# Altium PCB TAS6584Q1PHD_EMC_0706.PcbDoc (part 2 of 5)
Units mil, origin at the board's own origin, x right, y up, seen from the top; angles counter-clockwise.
Board outline 7086.61 x 5118.11 mil, 6 copper layers (Top Layer, GND02, SIG03, SIG04, GND05, Bottom Layer), stack 60.484 mil thick; 461 components, 247 nets, 1337 pads, 1658 vias.
Unrouted connection lines stored in the file: 67.
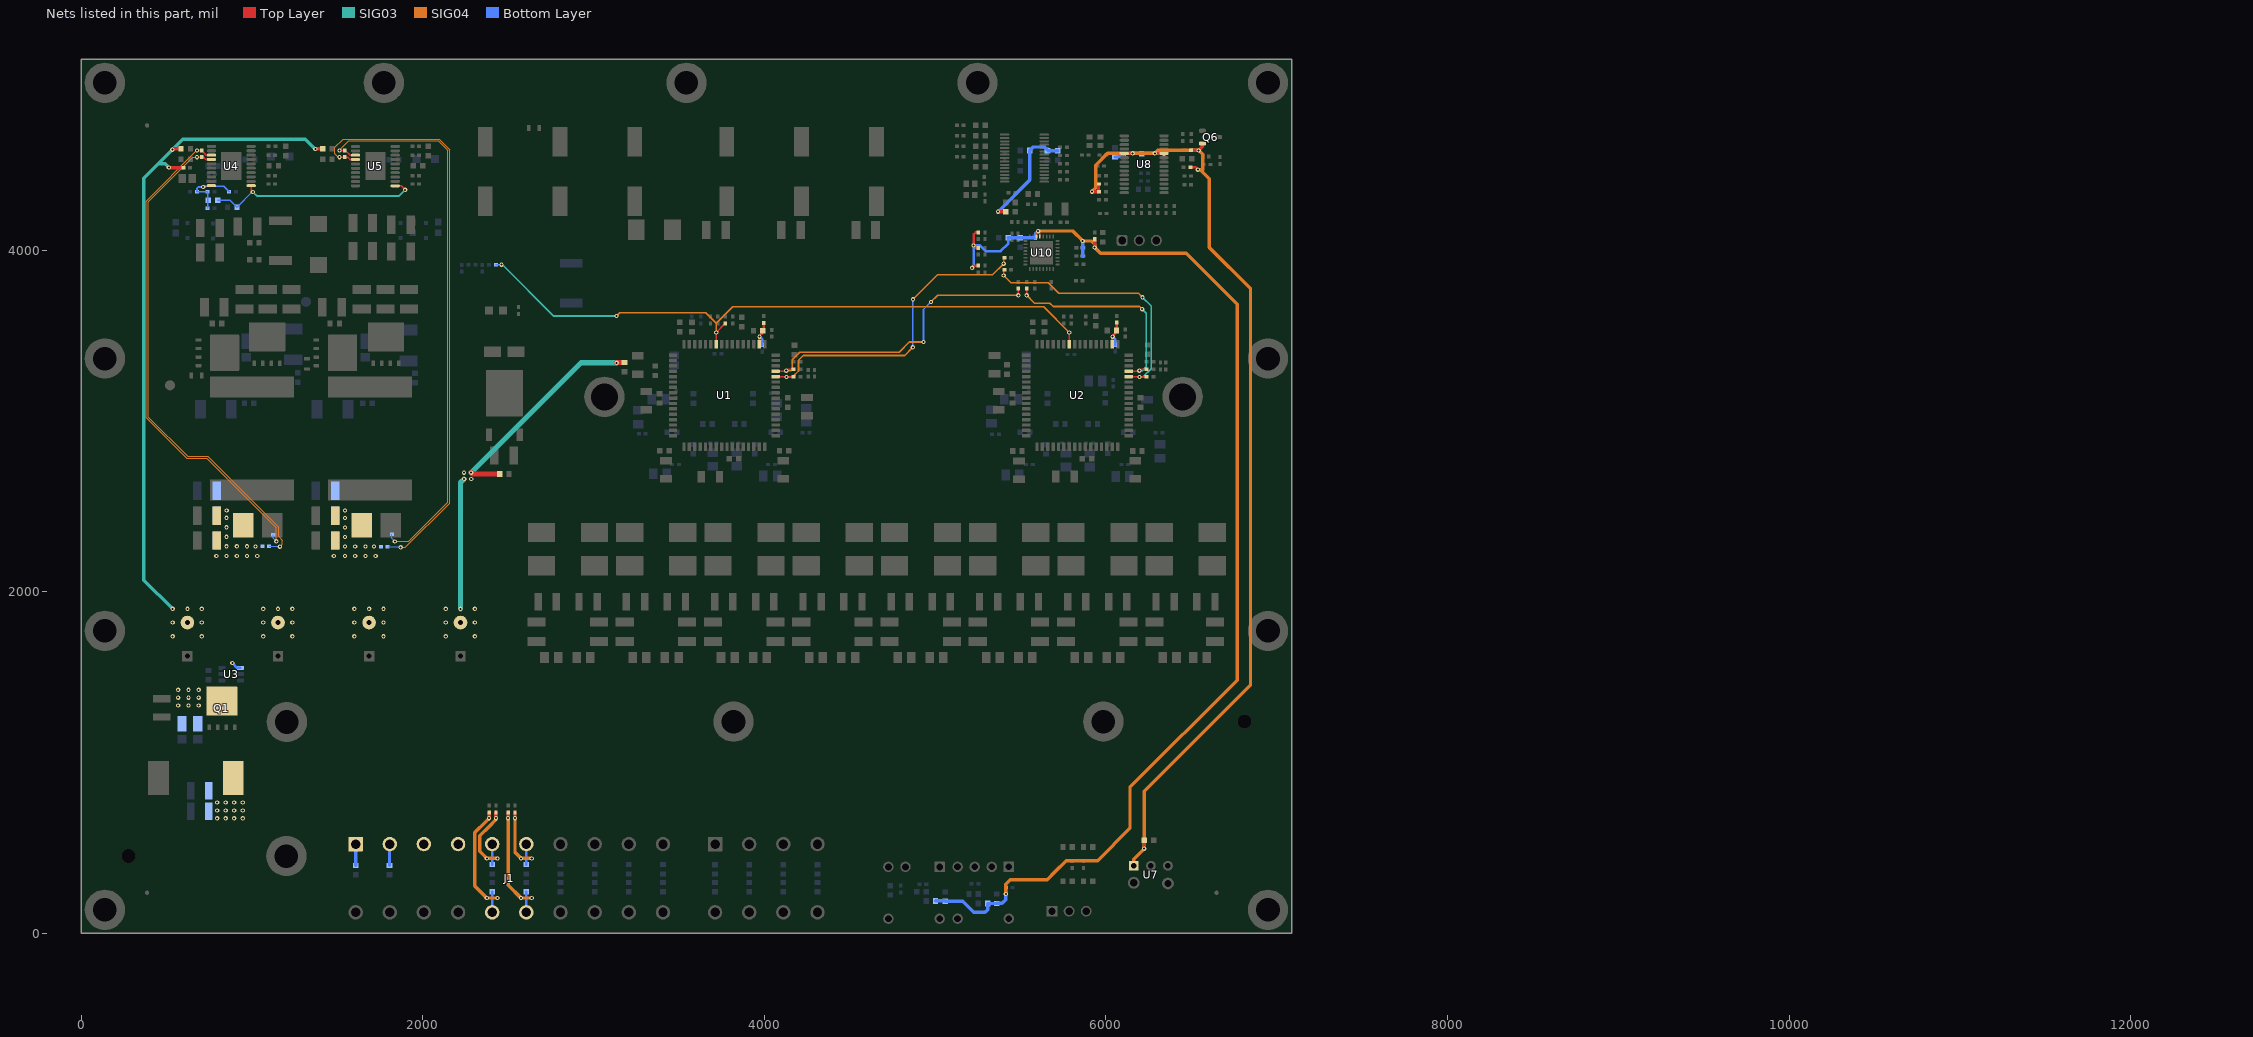
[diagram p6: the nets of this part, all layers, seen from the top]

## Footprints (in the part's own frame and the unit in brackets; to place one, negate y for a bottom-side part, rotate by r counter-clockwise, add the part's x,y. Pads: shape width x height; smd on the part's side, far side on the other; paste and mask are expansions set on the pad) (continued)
NDP0003B_N [mm] "D-PAK, 4-Leads, Body 6.1x6.6mm, Pitch 2.29mm, Lead Span 9.7mm, IPC Medium Density"
  rrect11% 1.9x0.95 smd: 1(-4.35,2.28) 3(-4.35,-2.28)
  rrect2% 6.9x5.5 smd: 4(1.85,0)
  silkscreen extent -4.47,-3.35 -2,3.43, body extent -2.5,-3.35 3.7,3.35, height 2.38
PA2512 [mm]
  rect 3.05x3.68 smd: 1(-2.16,0) 2(2.16,0)
  silkscreen extent -4,-2.2 4,2.2, body extent -3.3,-1.71 3.3,1.71, height 0.88
Panasonic_B [mm] "SMD, 2-Leads, Dia 4mm"
  rrect6% 2.5x1.6 smd: 1(-1.75,0) 2(1.75,0)
  silkscreen extent -2,-2.15 2.15,2.15, body extent -2.15,-2.15 2.15,2.15, height 6.1
PLR135_T10 [mm] "EVERLIGHT"
  rect 1.45x1.45 hole 0.813: 1(2.54,-4.67)
  round 1.45 hole 0.813: 2(0,-4.67) 3(-2.54,-4.67)
  round 1.75 hole 1.092: 4(2.54,-2.13) 5(-2.54,-2.04)
  silkscreen extent -5.05,-6.93 5.05,6.95, body extent -5,-6.9 5,6.9, height 10.3
PW0028A_N [mm] "TSOP, 28-Leads, Body 9.7x4.4mm, Pitch 0.65mm, IPC Medium Density"
  oval 1.4x0.45 smd: 1(-2.95,4.225) 2(-2.95,3.575) 3(-2.95,2.925) 4(-2.95,2.275) 5(-2.95,1.625) 6(-2.95,0.975) 7(-2.95,0.325) 8(-2.95,-0.325) 9(-2.95,-0.975) 10(-2.95,-1.625) 11(-2.95,-2.275) 12(-2.95,-2.925) 13(-2.95,-3.575) 14(-2.95,-4.225) 15(2.95,-4.225) 16(2.95,-3.575) 17(2.95,-2.925) 18(2.95,-2.275) 19(2.95,-1.625) 20(2.95,-0.975) 21(2.95,-0.325) 22(2.95,0.325) 23(2.95,0.975) 24(2.95,1.625) 25(2.95,2.275) 26(2.95,2.925) 27(2.95,3.575) 28(2.95,4.225)
  silkscreen extent -3.5,-4.9 1.5,4.9, body extent -3.21,-4.85 3.21,4.85, height 1
PWP0020A_N [mm] "TSOP, 20-Leads, Body 6.5x4.4mm, Pitch 0.65mm, Exposed Pad, IPC Medium Density"
  rrect100% 1.4x0.45 smd: 1(-2.95,2.925) 2(-2.95,2.275) 3(-2.95,1.625) 4(-2.95,0.975) 5(-2.95,0.325) 6(-2.95,-0.325) 7(-2.95,-0.975) 8(-2.95,-1.625) 9(-2.95,-2.275) 10(-2.95,-2.925) 11(2.95,-2.925) 12(2.95,-2.275) 13(2.95,-1.625) 14(2.95,-0.975) 15(2.95,-0.325) 16(2.95,0.325) 17(2.95,0.975) 18(2.95,1.625) 19(2.95,2.275) 20(2.95,2.925)
  rrect3% 3x4.2 smd: 21(0,0)
  silkscreen extent -3.55,-3.3 1.5,3.4, body extent -3.21,-3.25 3.21,3.25, height 1
QFP64-PHD [mm] "TQFP, 64-Leads, Body 14x14mm, Pitch 0.8mm, Thermal Pad 8x8mm, IPC High Density"
  rrect20% 1.25x0.5 smd: 1(-7.625,6) 2(-7.625,5.2) 3(-7.625,4.4) 4(-7.625,3.6) 5(-7.625,2.8) 6(-7.625,2) 7(-7.625,1.2) 8(-7.625,0.4) 9(-7.625,-0.4) 10(-7.625,-1.2) 11(-7.625,-2) 12(-7.625,-2.8) 13(-7.625,-3.6) 14(-7.625,-4.4) 15(-7.625,-5.2) 16(-7.625,-6) 33(7.625,-6) 34(7.625,-5.2) 35(7.625,-4.4) 36(7.625,-3.6) 37(7.625,-2.8) 38(7.625,-2) 39(7.625,-1.2) 40(7.625,-0.4) 41(7.625,0.4) 42(7.625,1.2) 43(7.625,2) 44(7.625,2.8) 45(7.625,3.6) 46(7.625,4.4) 47(7.625,5.2) 48(7.625,6)
  rrect20% 0.5x1.25 smd: 17(-6,-7.625) 18(-5.2,-7.625) 19(-4.4,-7.625) 20(-3.6,-7.625) 21(-2.8,-7.625) 22(-2,-7.625) 23(-1.2,-7.625) 24(-0.4,-7.625) 25(0.4,-7.625) 26(1.2,-7.625) 27(2,-7.625) 28(2.8,-7.625) 29(3.6,-7.625) 30(4.4,-7.625) 31(5.2,-7.625) 32(6,-7.625) 49(6,7.625) 50(5.2,7.625) 51(4.4,7.625) 52(3.6,7.625) 53(2.8,7.625) 54(2,7.625) 55(1.2,7.625) 56(0.4,7.625) 57(-0.4,7.625) 58(-1.2,7.625) 59(-2,7.625) 60(-2.8,7.625) 61(-3.6,7.625) 62(-4.4,7.625) 63(-5.2,7.625) 64(-6,7.625)
  silkscreen extent -8.13,-7.12 7.12,7.12, body extent -7.02,-7.02 7.02,7.02, height 1.21
RHB0032E [mm] "QFN, 32-Leads, Body 5x5mm, Pitch 0.5mm, Thermal Pad 3.45x3.45mm, TI Recommended"
  oval 0.6x0.24 smd: 1(-2.4,1.75) 2(-2.4,1.25) 3(-2.4,0.75) 4(-2.4,0.25) 5(-2.4,-0.25) 6(-2.4,-0.75) 7(-2.4,-1.25) 8(-2.4,-1.75) 17(2.4,-1.75) 18(2.4,-1.25) 19(2.4,-0.75) 20(2.4,-0.25) 21(2.4,0.25) 22(2.4,0.75) 23(2.4,1.25) 24(2.4,1.75)
  oval 0.24x0.6 smd: 9(-1.75,-2.4) 10(-1.25,-2.4) 11(-0.75,-2.4) 12(-0.25,-2.4) 13(0.25,-2.4) 14(0.75,-2.4) 15(1.25,-2.4) 16(1.75,-2.4) 25(1.75,2.4) 26(1.25,2.4) 27(0.75,2.4) 28(0.25,2.4) 29(-0.25,2.4) 30(-0.75,2.4) 31(-1.25,2.4) 32(-1.75,2.4)
  rect 3.45x3.45 smd paste-1.725: 33(0,0)
  silkscreen extent -2.72,-2.73 2.72,2.73, body extent -2.57,-2.57 2.58,2.58, height 1.01
SOD-123F [mm] "NXP recommended land pattern"
  rect 1.2x1.2 smd paste-0.05: 1(-1.4,0) 2(1.4,0)
  silkscreen extent -2.64,-1.12 2.01,1.12, body extent -1.8,-0.85 1.8,0.85, height 1.2
SOD-123HE [mm] "SMD, 2-Leads, Body 2.8x1.8mm"
  rect 2.3x1.4 smd: 1(-0.9,0)
  rect 1.25x1.4 smd: 2(1.425,0)
  silkscreen extent -2.7,-1.1 2,1.1, body extent -1.5,-0.98 1.5,0.98, height 1
SOD-323 [mm] "NXP recommended land pattern"
  rect 0.6x0.6 smd paste-0.05: 1(-1.1,0) 2(1.1,0)
  silkscreen extent -2.06,-0.86 1.53,0.86, body extent -1.3,-0.67 1.3,0.68, height 1.1
SOT-23 [mm] "SOT23, 3-Leads, Body 2.9x1.3mm, Pitch 0.95mm, Lead Span 2.5mm, IPC Medium Density"
  rrect50% 1x0.6 smd: 1(-1.2,0.95) 2(-1.2,-0.95) 3(1.2,0)
  silkscreen extent -1.63,-1.5 0.7,1.5, body extent -1.16,-1.45 1.21,1.45, height 1
SRP1265a [mm] "BOURNS"
  rect 3.1x5 smd: 1(-5.55,0) 2(5.55,0)
  silkscreen extent -7,-6.5 7,6.5, body extent -6.95,-6.4 6.95,6.4, height 6.4
SRP1770TA [mm] "SMD, 2-Leads, Body 16.9x16.9mm"
  rect 3.15x12.5 smd: 1(-7.675,0) 2(7.675,0)
  silkscreen extent -8.45,-8.45 8.45,8.45, body extent -8.65,-8.45 8.65,8.45, height 6.7
SRP7030F_3 [mm] "BOURNS"
  rect 2.4x2.5 smd: 1(-3.1,0) 2(3,0)
  silkscreen extent -3.4,-3.4 3.4,3.4, body extent -3.35,-3.35 3.35,3.35, height 3
TI_Stacked_Overlay_Small [mil]
  silkscreen extent -418,-98 418,98
WEEE_Minimum [mil] "WEEElie bin"
  silkscreen extent -95,-172 99,104
Wurth_61300311021 [mm] "Header, 2.54 mm, 3x1, R/A, TH"
  rect 1.6x1.6 hole 1.1: 1(-2.54,0)
  round 1.6 hole 1.1: 2(0,0) 3(2.54,0)
  silkscreen extent -4.25,-4.04 3.81,-1.5, body extent -3.81,-10.04 3.81,0.32, height 2.55
WURTH_61300311121 [mm] "Header, 2.54mm, 3x1, TH"
  rrect50% 1.65x1.65 hole 1.15: 1(-2.54,0)
  round 1.65 hole 1.15: 2(0,0) 3(2.54,0)
  body extent -3.81,-1.27 3.81,1.27, height 8.54
XTAL_ABM10 [mm] "ABRACON"
  rect 0.8x0.9 smd: 1(-0.625,0.825) 2(-0.625,-0.825) 3(0.625,-0.825) 4(0.625,0.825)
  silkscreen extent -1.28,-0.13 1.05,1.52, body extent -1.05,-1.3 1.05,1.3, height 0.7

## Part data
C1 C10 C11 C13 C14 C59 C68 C69 C71 C72 C124 C127 C137 C141 C181 C203 C219: library part CMP-0007139-1, "CAP, CERM, 1 uF, 25 V, +/- 10%, X7R, AEC-Q200 Grade 1, 0603", Cap_Case=0603, Manufacturer=MuRata, Supplier Part Number 1=490-10673-1-ND, TempCo=X7R, Tolerance_%=10%, Value1=Unknown, Value2=25V, ValueDisplayed=1uF
C2 C3 C4 C5 C17 C18 C60 C61 C62 C63 C75 C76: library part CMP-0750040-1, "CAP, CERM, 1 µF, 100 V,+/- 10%, X7R, AEC-Q200 Grade 1, 1206", Cap_Case=1206, Manufacturer=MuRata, TempCo=X7R, Tolerance_%=10%, Value2=100V, ValueDisplayed=1µF
C6 C7 C8 C9 C15 C16 C64 C65 C66 C67 C73 C74: library part CMP-0064935-4, "CAP, CERM, 0.1 uF, 100 V,+/- 10%, X7R, AEC-Q200 Grade 1, 0603", Cap_Case=0603, Manufacturer=MuRata, Supplier Part Number 1=490-13420-1-ND, TempCo=X7R, Tolerance_%=10%, Value1=Unknown, Value2=100V, ValueDisplayed=0.1uF
C12 C70 C128: library part CMP-0083622-1, "CAP, CERM, 2.2 µF, 25 V,+/- 10%, X7R, AEC-Q200 Grade 1, 0805", Cap_Case=0805, Manufacturer=MuRata, Supplier Part Number 1=490-4787-1-ND, TempCo=X7R, Tolerance_%=10%, Value2=25V, ValueDisplayed=2.2µF
C19 C20 C21 C22 C23 C24 C25 C26 C77 C78 C79 C80 C81 C82 C83 C84 C132 C144: library part CMP-0007145-1, "CAP, CERM, 0.22 uF, 50 V, +/- 10%, X7R, AEC-Q200 Grade 1, 0603", Cap_Case=0603, Manufacturer=MuRata, Supplier Part Number 1=490-5402-1-ND, TempCo=X7R, Tolerance_%=10%, Value1=Unknown, Value2=50V, ValueDisplayed=0.22uF
C27 C28 C29 C30 C31 C32 C33 C34 C85 C86 C87 C88 C89 C90 C91 C92: library part CMP-0006707-2, "CAP, CERM, 330 pF, 100 V, +/- 10%, X7R, 0402", Cap_Case=0402, Manufacturer=MuRata, Supplier Part Number 1=GRM155R72A331KA01D-ND, TempCo=X7R, Tolerance_%=10%, Value1=Unknown, Value2=100V, ValueDisplayed=330pF
C35 C36 C37 C38 C39 C40 C41 C42 C93 C94 C95 C96 C97 C98 C99 C100: library part CMP-0009232-1, "CAP, CERM, 2.2 uF, 100 V, +/- 10%, X7R, 1210", Cap_Case=1210, Manufacturer=MuRata, Supplier Part Number 1=490-3385-1-ND, TempCo=X7R, Tolerance_%=10%, Value1="0.007 ohm", Value2=100V, ValueDisplayed=2.2uF
C43 C44 C45 C46 C47 C48 C49 C50 C101 C102 C103 C104 C105 C106 C107 C108: library part CMP-0008022-1, "CAP, CERM, 0.47 uF, 50 V, +/- 10%, X7R, AEC-Q200 Grade 1, 0805", Cap_Case=0805, Manufacturer=MuRata, PartNumber=GCM21BR71H474KA55L, Supplier Part Number 1=490-4788-1-ND, TempCo=X7R, Tolerance_%=10%, Value1=Unknown, Value2=50V, ValueDisplayed=0.47uF
C51 C52 C53 C54 C55 C56 C57 C58 C109 C110 C111 C112 C113 C114 C115 C116 C122 C190 C191 C192 C193: library part CMP-0007174-3, "CAP, CERM, 0.01 uF, 50 V, +/- 5%, C0G/NP0, 0603", Cap_Case=0603, Manufacturer=MuRata, Supplier Part Number 1=490-9666-1-ND, TempCo=C0G/NP0, Tolerance_%=5%, Value1=Unknown, Value2=50V, ValueDisplayed=0.01uF
C117 C119 C126: library part CMP-0009228-2, "CAP, CERM, 4.7 uF, 50 V, +/- 10%, X7R, 1210", Cap_Case=1210, Manufacturer=MuRata, Supplier Part Number 1=490-1864-1-ND, TempCo=X7R, Tolerance_%=10%, Value1="0.002 ohm", Value2=50V, ValueDisplayed=4.7uF
C118 C184: library part CMP-0007463-1, "CAP, CERM, 0.068 uF, 50 V, +/- 10%, X7R, 0603", Cap_Case=0603, Manufacturer=MuRata, Supplier Part Number 1=490-3288-1-ND, TempCo=X7R, Tolerance_%=10%, Value1=Unknown, Value2=50V, ValueDisplayed=0.068uF
C120 C123 C187 C189: library part CMP-0007203-1, "CAP, CERM, 270 pF, 50 V, +/- 5%, C0G/NP0, 0603", Cap_Case=0603, Manufacturer=MuRata, Supplier Part Number 1=490-1437-1-ND, TempCo=C0G/NP0, Tolerance_%=5%, Value1=Unknown, Value2=50V, ValueDisplayed=270pF
C121 C158 C159 C166 C167: library part CMP-0007470-1, "CAP, CERM, 0.1 uF, 100 V, +/- 10%, X7R, 0603", Cap_Case=0603, Manufacturer=MuRata, Supplier Part Number 1=490-6439-1-ND, TempCo=X7R, Tolerance_%=10%, Value1=Unknown, Value2=100V, ValueDisplayed=0.1uF
C125 C129 C179 C182 C201 C205 C207 C209 C212 C213 C228 C229 C230: "CAP, CERM, 0.1 uF, 16 V, +/- 10%, X7R, 0402", Cap_Case=0402, Manufacturer=MuRata, PartNumber=GRM155R71C104KA88D, Supplier Part Number 1=490-3261-1-ND, TempCo=X7R, Tolerance_%=10%, Value1=Unknown, Value2=16V, ValueDisplayed=0.1uF
C130 C142: library part CMP-0006682-1, "CAP, CERM, 220 pF, 50 V, +/- 10%, X7R, 0402", Cap_Case=0402, Manufacturer=MuRata, Supplier Part Number 1=490-1298-1-ND, TempCo=X7R, Tolerance_%=10%, Value1=Unknown, Value2=50V, ValueDisplayed=220pF
C131 C133 C135 C136: library part CMP-0093073-1, "2200 µF 25 V Aluminum Electrolytic Capacitors Radial, Can - 10000 Hrs @ 105°C", Digikey Part Number=493-6873-ND, Leakage Current=550uA, Manufacturer=Nichicon, Mouser Part Number=647-UHW1E222MHD, Operating Temperature Range="-40°C to +105°C", Tolerance_%=20%, ValueDisplayed=2200uF
C134 C145: library part CMP-0007498-1, "CAP, CERM, 4.7 uF, 10 V, +/- 20%, X7R, 0603", Cap_Case=0603, Manufacturer=MuRata, TempCo=X7R, Tolerance_%=20%, Value1=Unknown, Value2=10V, ValueDisplayed=4.7uF
C138 C139 C140 C146 C147 C148 C149 C150 C151 C152 C153 C160 C161 C162 C163 C164 C165 C168 C220 C221 C222 C223 C224 C225 C226 C227: library part CMP-0009226-3, "CAP, CERM, 10 uF, 50 V, +/- 10%, X7R, 1210", Cap_Case=1210, Manufacturer=MuRata, Supplier Part Number 1=490-6544-1-ND, TempCo=X7R, Tolerance_%=10%, Value1=Unknown, Value2=50V, ValueDisplayed=10uF
C143: library part CMP-0860542-1, "CAP, AL, 47 µF, 16 V, +/- 20%, 0.85 ohm, AEC-Q200 Grade 2, SMD", Cap_Case=B, Manufacturer=Panasonic, Tolerance_%=20%, Value1="0.85 ohm", Value2=16V, ValueDisplayed=47µF
C154 C155 C156 C157 C218: library part CMP-0007131-1, "CAP, CERM, 1000 pF, 100 V, +/- 5%, C0G/NP0, AEC-Q200 Grade 1, 0603", Cap_Case=0603, Manufacturer=MuRata, Supplier Part Number 1=490-4772-1-ND, TempCo=C0G/NP0, Tolerance_%=5%, Value1=Unknown, Value2=100V, ValueDisplayed=1000pF
C169 C170 C171 C172 C173 C174: library part CMP-0093066-1, "330 µF 50 V Aluminum Electrolytic Capacitors Radial, Can - SMD 120mOhm @ 100kHz 2000 Hrs @ 105°C", Digikey Part Number=565-5155-1-ND, Leakage Current=165uA, Manufacturer="United Chemi-Con", Mouser Part Number=661-EMZR500ARA331MJA, Operating Temperature Range="-55°C to +105°C", Tolerance_%=20%, ValueDisplayed=330uF
C175 C176 C194 C195 C196 C197 C198 C202 C204 C206 C208 C210 C211 C214 C215: library part CMP-0007497-1, "CAP, CERM, 10 uF, 10 V, +/- 20%, X7R, 0603", Cap_Case=0603, Manufacturer=MuRata, Supplier Part Number 1=81-GRM188Z71A106MA3D, TempCo=X7R, Tolerance_%=20%, Value1=Unknown, Value2=10V, ValueDisplayed=10uF
C177 C180 C199 C200: library part CMP-0006436-1, "CAP, CERM, 20 pF, 50 V, +/- 5%, C0G/NP0, 0402", Cap_Case=0402, Manufacturer=MuRata, Supplier Part Number 1=81-GRM1555C1H200JA1D, TempCo=C0G/NP0, Tolerance_%=5%, Value1=Unknown, Value2=50V, ValueDisplayed=20pF
C178 C185 C186 C188: "CAP, CERM, 10 pF, 50 V, +/- 5%, C0G/NP0, 0402", Cap_Case=0402, Manufacturer=MuRata, PartNumber=GRM1555C1H100JA01D, Supplier Part Number 1=81-GRM1555C1H100JA1D, TempCo=C0G/NP0, Tolerance_%=5%, Value1=Unknown, Value2=50V, ValueDisplayed=10pF
C183: "CAP, CERM, 4700 pF, 25 V, +/- 10%, X7R, 0402", Cap_Case=0402, Manufacturer=MuRata, PartNumber=GRM155R71E472KA01D, Supplier Part Number 1=490-1309-1-ND, TempCo=X7R, Tolerance_%=10%, Value1=Unknown, Value2=25V, ValueDisplayed=4700pF
C216 C217: library part CMP-0006375-1, "CAP, CERM, 12 pF, 25 V, +/- 5%, C0G/NP0, 0402", Cap_Case=0402, Manufacturer=MuRata, Supplier Part Number 1=81-GRM1555C1E120JA1D, TempCo=C0G/NP0, Tolerance_%=5%, Value1=Unknown, Value2=25V, ValueDisplayed=12pF
D1 D2 D10 D11: library part CMP-0028825-2, "Diode, Schottky, 60 V, 3 A, AEC-Q101, SOD-123HE", Manufacturer="Fairchild Semiconductor", Value1=3A, Value2=0.65V
D3 D4: library part CMP-0028377-1, "Diode, Schottky, 60 V, 1 A, SOD-123F", Manufacturer=Nexperia, Supplier Part Number 1=568-4104-1-ND, Value1=1A, Value2=0.57V
D5: "LED, Green, SMD", Color=Green, Manufacturer=Lite-On, PartNumber=LTST-C170KGKT, Supplier Part Number 1=160-1414-1-ND, Value1=W, Value2=2V
D6 D7 D8 D9: library part CMP-0028455-1, "Diode, Schottky, 30 V, 0.2 A, SOD-323", Manufacturer="ON Semiconductor", Supplier Part Number 1=BAT54HT1OSCT-ND, Value1=0.2A, Value2=0.35V
D12 D13: "LED, Blue, SMD", Color=blue, Manufacturer=Rohm, PartNumber=SMLP12BC7TT86, Supplier Part Number 1=511-1615-1-ND, Value1=W, Value2=2.9V
FID1 FID2 FID3 FID4 FID5 FID6: library part CMP-0077181-1, "Fiducial mark.  There is nothing to buy or mount.", Manufacturer=N/A
H1: library part Heatsink, "TAS6584 EMI board heatsink", Alternate Manufacturer=-
J1: library part CMP-0087217-1, "TERM BLOCK HDR 20POS 5.08MM", Current_A=10A, Manufacturer="Phoenix Contact", Voltage_V=320V
J2: library part CMP-0093062-1, Current_A=10A, Digikey Part Number=277-1401-ND, Manufacturer="Phoenix Contact", Mouser Part Number=651-1736713, Operating Temperature Range="-40°C to +100°C", Voltage_V=320V
J3: library part CMP-0054795-1, "Header, 2.54 mm, 3x1, Gold, R/A, TH", Color=Black, Manufacturer="Wurth Elektronik", Supplier Part Number 1=732-5336-ND
J4: library part CMP-0054796-2, "Header, 2.54 mm, 3x1, Gold, TH", Color=Black, Manufacturer="Wurth Elektronik", Supplier Part Number 1=732-5316-ND
J5: library part CMP-0075020-1, "JUMPER TIN SMD", Manufacturer=Harwin, PartNumber=S1911-46R, Supplier Part Number 1=952-1740-1-ND
L1 L11 L15 L16 L17 L18 L19: library part CMP-0003347-2, "Ferrite Bead, 600 ohm @ 100 MHz, 0.5 A, 0603", Manufacturer=MuRata, Supplier Part Number 1=490-11031-1-ND, Value1="0.35 ohm", Value2=0.5A, ValueDisplayed="600 ohm"
L2 L3 L4 L5 L6 L7 L8 L9: library part CMP-0093075-1, "Power Choke Coil, 10uH 20% 100kHz, 22mΩ DCR max, Idc 5.8A, Isat 10A", Manufacturer=Cyntec, Operating Temperature Range="-55°C to +125°C", Test Frequency=100kHz, Tolerance_%=20%
L10: library part CMP-0056908-1, "Inductor, Shielded, 1 uH, 30 A, 0.0017 ohm, AEC-Q200 Grade 0, SMD", Manufacturer=Bourns, Supplier Part Number 1=SRP1265A-1R0MCT-ND, Value1="0.0017 ohm", Value2=30A, ValueDisplayed=1uH
L12 L13: library part CMP-0081211-1, "Inductor, Shielded, Powdered Iron, 4.7 µH, 25 A, 0.0055 ohm, AEC-Q200 Grade 0, SMD", Manufacturer=Bourns, Supplier Part Number 1=SRP1770TA-4R7MCT-ND, Value1="0.0055 ohm", Value2=25A, ValueDisplayed=4.7µH
L14: library part CMP-0056994-1, "Inductor, Flat Wire, Powdered Iron, 200 nH, 23 A, 0.0024 ohm, SMD", Manufacturer=Bourns, Supplier Part Number 1=652-SRP7030-R20FM, Value1="0.0024 ohm", Value2=23A, ValueDisplayed=200nH
Logo1: library part CMP-0074838-1, "Texas Instrument Corporate Signature"
Logo2: library part CMP-0074847-1, "FCC_disclaimer"
Logo3: library part CMP-0074769-1
Logo4: library part CMP-0074844-1
MP1: library part CMP-0093198-1, Digikey Part Number=732-3670378-ND, Manufacturer="Wurth Electronics", Mouser Part Number=710-3670378, Operating Temperature Range="-40°C to +125°C"
MP2: library part CMP-0093199-1, Digikey Part Number=732-3670548-ND, Manufacturer="Wurth Electronics", Mouser Part Number=710-3670548, Operating Temperature Range="-40°C to +125°C"
Q1: library part CMP-0000274-1, "MOSFET, N-CH, 25 V, 100 A, DNK0008A (VSON-CLIP-8)", Alternate Manufacturer=None, Manufacturer="Texas Instruments", Supplier Part Number 1=CSD16570Q5B-ND, Value1=0, Value2="192 nC"
Q2 Q3 Q4 Q5: library part CMP-0000823-2, "MOSFET, N-CH, 60 V, 100 A, DNK0008A (VSON-CLIP-8)", Alternate Manufacturer=None, Manufacturer="Texas Instruments", Supplier Part Number 1=296-41076-1-ND, Value1=0.003, Value2="41 nC"
Q6: library part CMP-0000325-2, "Transistor, PNP, 40 V, 0.2 A, SOT-23", Manufacturer="Fairchild Semiconductor", Supplier Part Number 1=MMBT3906FSCT-ND, Value1="0.2 A", Value2=300
R1 R3 R5: library part CMP-0026231-2, "RES, 2.20 k, 1%, 0.063 W, AEC-Q200 Grade 0, 0402", Manufacturer=Vishay-Dale, Power_W=63mW, Supplier Part Number 1=541-2.20KLCT-ND, TempCo="100 ppm/C", Tolerance_%=1%, Value2=0.063W, Value_Code=2k20, ValueDisplayed=2.20k
R2 R4 R6 R7 R10 R11 R32 R33 R35 R36 R39 R40 R52 R65 R66 R75 R127 R128 R129 R130 R131 R132 R133 R134 R135 R155 R157 R160: "RES, 10.0 k, 1%, 0.063 W, AEC-Q200 Grade 0, 0402", Manufacturer=Vishay-Dale, PartNumber=CRCW040210K0FKED, Power_W=63mW, Supplier Part Number 1=541-10.0KLCT-ND, TempCo="100 ppm/C", Tolerance_%=1%, Value2=0.063W, Value_Code=10k0, ValueDisplayed=10.0k
R8 R38 R67: library part CMP-0026822-3, "RES, 0, 5%, 0.063 W, AEC-Q200 Grade 0, 0402", Manufacturer=Vishay-Dale, PartNumber=CRCW04020000Z0ED, Power_W=63mW, Supplier Part Number 1=541-0.0JCT-ND, TempCo="200 ppm/C", Tolerance_%=5%, Value2=0.063W, Value_Code=0000, ValueDisplayed=0
R9 R12 R14 R15 R37 R41 R43 R44 R76 R77 R83 R84 R125 R126 R144 R145 R146 R147 R149 R151 R152 R153 R154 R158 R159: library part CMP-0026822-3, "RES, 0, 5%, 0.063 W, AEC-Q200 Grade 0, 0402", Manufacturer=Vishay-Dale, Power_W=63mW, Supplier Part Number 1=541-0.0JCT-ND, TempCo="200 ppm/C", Tolerance_%=5%, Value2=0.063W, Value_Code=0000, ValueDisplayed=0
R13 R42: library part CMP-0025958-3, "RES, 10.0 k, 1%, 0.063 W, AEC-Q200 Grade 0, 0402", Manufacturer=Vishay-Dale, PartNumber=CRCW040210K0FKED, Power_W=63mW, Supplier Part Number 1=541-10.0KLCT-ND, TempCo="100 ppm/C", Tolerance_%=1%, Value2=0.063W, Value_Code=10k0, ValueDisplayed=10.0k
R16 R17 R18 R19 R20 R21 R22 R23 R34 R45 R46 R47 R48 R49 R50 R51: library part CMP-0020448-3, "RES, 10, 5%, 0.125 W, AEC-Q200 Grade 0, 0805", Manufacturer=Vishay-Dale, Power_W=125mW, Supplier Part Number 1=541-10ACT-ND, TempCo="200 ppm/C", Tolerance_%=5%, Value2=0.125W, Value_Code=10R0, ValueDisplayed=10
R24 R25 R26 R27 R28 R29 R30 R31 R53 R54 R55 R56 R57 R58 R59 R60 R103 R104 R105: library part CMP-0015361-2, "RES, 0, 5%, 0.25 W, 1210", Manufacturer=Rohm, Power_W=250mW, Supplier Part Number 1=RHM0.0BECT-ND, TempCo="20 ppm/C", Tolerance_%=5%, Value2=0.25W, Value_Code=0000, ValueDisplayed=0
R61: library part CMP-0025950-1, "RES, 100 k, 1%, 0.063 W, 0402", Manufacturer=Vishay-Dale, Power_W=63mW, Supplier Part Number 1=541-100KLCT-ND, TempCo="100 ppm/C", Tolerance_%=1%, Value2=0.063W, Value_Code=100k
R62: library part CMP-0026506-1, "RES, 68.1 k, 1%, 0.063 W, 0402", Manufacturer=Vishay-Dale, Power_W=63mW, Supplier Part Number 1=541-68.1KLCT-ND, TempCo="100 ppm/C", Tolerance_%=1%, Value2=0.063W, Value_Code=68k1, ValueDisplayed=68.1k
R63: library part CMP-0026336-2, "RES, 3.57 k, 1%, 0.063 W, AEC-Q200 Grade 0, 0402", Manufacturer=Vishay-Dale, Power_W=63mW, Supplier Part Number 1=541-3.57KLCT-ND, TempCo="100 ppm/C", Tolerance_%=1%, Value2=0.063W, Value_Code=3k57, ValueDisplayed=3.57k
R64 R72: library part CMP-0026542-2, "RES, 750, 1%, 0.063 W, AEC-Q200 Grade 0, 0402", Manufacturer=Vishay-Dale, Power_W=63mW, Supplier Part Number 1=541-750LCT-ND, TempCo="100 ppm/C", Tolerance_%=1%, Value2=0.063W, Value_Code=750R, ValueDisplayed=750
R69: library part CMP-0026284-2, "RES, 30.1 k, 1%, 0.063 W, AEC-Q200 Grade 0, 0402", Manufacturer=Vishay-Dale, Power_W=63mW, Supplier Part Number 1=541-30.1KLCT-ND, TempCo="100 ppm/C", Tolerance_%=1%, Value2=0.063W, Value_Code=30k1, ValueDisplayed=30.1k
R70: library part CMP-0026556-2, "RES, 7.68 k, 1%, 0.063 W, AEC-Q200 Grade 0, 0402", Manufacturer=Vishay-Dale, Power_W=63mW, Supplier Part Number 1=541-7.68KLCT-ND, TempCo="100 ppm/C", Tolerance_%=1%, Value2=0.063W, Value_Code=7k68, ValueDisplayed=7.68k
R71 R81 R138 R142: library part CMP-0025805-4, "RES, 3.3, 5%, 0.1 W, AEC-Q200 Grade 0, 0603", Manufacturer=Vishay-Dale, Power_W=100mW, Supplier Part Number 1=541-3.3GCT-ND, TempCo="200 ppm/C", Tolerance_%=5%, Value2=0.1W, Value_Code=3R30, ValueDisplayed=3.3
R73 R74 R82: library part CMP-0026162-2, "RES, 20.0 k, 1%, 0.063 W, AEC-Q200 Grade 0, 0402", Manufacturer=Vishay-Dale, Power_W=63mW, Supplier Part Number 1=541-20.0KLCT-ND, TempCo="100 ppm/C", Tolerance_%=1%, Value2=0.063W, Value_Code=20k0, ValueDisplayed=20.0k
R80 R139 R140 R141 R148 R150: library part CMP-0026822-3, "RES, 0, 5%, 0.063 W, AEC-Q200 Grade 0, 0402", Manufacturer=Vishay-Dale, PartNumber=CRCW04020000Z0ED, Power_W=63mW, Supplier Part Number 1=541-0.0JCT-ND, TempCo="200 ppm/C", Tolerance_%=5%, Value2=0.063W, Value_Code=0000
R86 R124 R136 R137 R143: library part CMP-0026852-3, "RES, 1.0 k, 5%, 0.063 W, AEC-Q200 Grade 0, 0402", Manufacturer=Vishay-Dale, Power_W=63mW, Supplier Part Number 1=541-1.0KJCT-ND, TempCo="200 ppm/C", Tolerance_%=5%, Value2=0.063W, Value_Code=1k00, ValueDisplayed=1.0k
R87 R88 R91 R92: library part CMP-0026852-1, "RES, 1.0 k, 5%, 0.063 W, 0402", Manufacturer=Vishay-Dale, Power_W=63mW, Supplier Part Number 1=541-1.0KJCT-ND, TempCo="200 ppm/C", Tolerance_%=5%, Value2=0.063W, Value_Code=1k00, ValueDisplayed=1.0k
R89 R90: library part CMP-0015833-2, "RES, 0.003, 1%, 1 W, AEC-Q200 Grade 0, 2512", Manufacturer="Yageo America", Power_W=1W, Supplier Part Number 1=YAG2138CT-ND, TempCo="100 ppm/C", Tolerance_%=1%, Value_Code=3L000, ValueDisplayed=0.003
R93 R94 R99 R100: library part CMP-0016186-1, "RES, 8.2, 5%, 0.75 W, AEC-Q200 Grade 0, 2010", Manufacturer=Vishay-Dale, Power_W=750mW, Supplier Part Number 1=541-8.2WCT-ND, TempCo="200 ppm/C", Tolerance_%=5%, Value2=0.75W, Value_Code=8R20, ValueDisplayed=8.2
R95 R96 R97 R98: library part CMP-0025776-4, "RES, 2.0, 5%, 0.1 W, AEC-Q200 Grade 0, 0603", Manufacturer=Vishay-Dale, Power_W=100mW, Supplier Part Number 1=541-2.0GCT-ND, TempCo="200 ppm/C", Tolerance_%=5%, Value2=0.1W, Value_Code=2R00, ValueDisplayed=2.0
R101: library part CMP-0016021-1, "RES, 0.68, 5%, 1 W, 2512", Manufacturer=Panasonic, Power_W=1W, Supplier Part Number 1=PT.68UCT-ND, TempCo="200 ppm/C", Tolerance_%=5%, Value_Code=R680, ValueDisplayed=0.68
R102: library part CMP-0015431-1, "RES, 10.0 k, 1%, 1 W, AEC-Q200 Grade 0, 2512", Manufacturer=Vishay-Dale, Power_W=1W, Supplier Part Number 1=541-10.0KAFCT-ND, TempCo="100 ppm/C", Tolerance_%=1%, Value_Code=10k0, ValueDisplayed=10.0k
R106 R114 R115 R116 R117 R122 R123: "RES, 49.9, 1%, 0.063 W, AEC-Q200 Grade 0, 0402", Manufacturer=Vishay-Dale, PartNumber=CRCW040249R9FKED, Power_W=63mW, Supplier Part Number 1=541-49.9LCT-ND, TempCo="100 ppm/C", Tolerance_%=1%, Value2=0.063W, Value_Code=49R9, ValueDisplayed=49.9
R107: "RES, 100 k, 1%, 0.063 W, AEC-Q200 Grade 0, 0402", Manufacturer=Vishay-Dale, PartNumber=CRCW0402100KFKED, Power_W=63mW, Supplier Part Number 1=541-100KLCT-ND, TempCo="100 ppm/C", Tolerance_%=1%, Value2=0.063W, Value_Code=100k
R108 R113: library part CMP-0026414-2, "RES, 4.99 k, 1%, 0.063 W, AEC-Q200 Grade 0, 0402", Manufacturer=Vishay-Dale, PartNumber=CRCW04024K99FKED, Power_W=63mW, Supplier Part Number 1=541-4.99KLCT-ND, TempCo="100 ppm/C", Tolerance_%=1%, Value2=0.063W, Value_Code=4k99, ValueDisplayed=4.99k
R109 R111 R112 R119: "RES, 4.99 k, 1%, 0.063 W, AEC-Q200 Grade 0, 0402", Manufacturer=Vishay-Dale, PartNumber=CRCW04024K99FKED, Power_W=63mW, Supplier Part Number 1=541-4.99KLCT-ND, TempCo="100 ppm/C", Tolerance_%=1%, Value2=0.063W, Value_Code=4k99, ValueDisplayed=4.99k
R110: library part CMP-0026934-3, "RES, 470, 5%, 0.063 W, AEC-Q200 Grade 0, 0402", Manufacturer=Vishay-Dale, Power_W=63mW, Supplier Part Number 1=541-470JCT-ND, TempCo="200 ppm/C", Tolerance_%=5%, Value2=0.063W, Value_Code=470R, ValueDisplayed=470
R118: "RES, 681, 1%, 0.063 W, AEC-Q200 Grade 0, 0402", Manufacturer=Vishay-Dale, PartNumber=CRCW0402681RFKED, Power_W=63mW, Supplier Part Number 1=541-681LCT-ND, TempCo="100 ppm/C", Tolerance_%=1%, Value2=0.063W, Value_Code=681R, ValueDisplayed=681
R120 R121 R156: library part CMP-0025817-1, "RES, 4.7 k, 5%, 0.1 W, 0603", Manufacturer=Vishay-Dale, Power_W=100mW, Supplier Part Number 1=541-4.7KGCT-ND, TempCo="200 ppm/C", Tolerance_%=5%, Value2=0.1W, Value_Code=4k70, ValueDisplayed=4.7k
R161: library part CMP-0026935-3, "RES, 47 k, 5%, 0.063 W, AEC-Q200 Grade 0, 0402", Manufacturer=Vishay-Dale, Power_W=63mW, Supplier Part Number 1=541-47KJCT-ND, TempCo="200 ppm/C", Tolerance_%=5%, Value2=0.063W, Value_Code=47k0, ValueDisplayed=47k
RT1 RT2 RT3: library part CMP-0054545-2, "Thermistor NTC, 10.0k ohm, 0.5%, 0603", Manufacturer=MuRata, Power_W=100mW, Tolerance_%=0.5%
U1 U2: "20W Inductor-Less, Digital Input, Stereo, Closed-Loop Class-D Audio Amplifier with Enhanced Processing and and DirectPath HP Driver (DCP0038)", Alternate Manufacturer="Texas Instruments"
U3: library part CMP-0079180-1, "Low Iq Always ON Smart Diode Controller, DBV0006A (SOT-23-6)", Alternate Manufacturer="Texas Instruments", Alternate PartNumber=LM74700QDBVRQ1
U4 U5: library part CMP-0066110-1, "3-65V Wide Vin, Current Mode Synchronous Boost Controller with Multiphase Capability, PWP0020A (TSSOP-20)", Alternate Manufacturer="Texas Instruments", Alternate PartNumber=LM5122MHE/NOPB
U6: library part CMP-0070332-1, "800mA Low-Dropout Linear Regulator, 3-pin TO-252, Pb-Free", Manufacturer="Texas Instruments", PackageTopMarking=NSUZXYTT*LM1117*IDT-3.3, PowerWise=N
U7: "Photolink- Fiber Optic Receiver, TH", Manufacturer=Everlight, PartNumber=PLR135/T10, Supplier Part Number 1=1080-1433-ND
U8: library part CMP-0028713-1, "Automotive Catalog 96-kHz 24-Bit Digital Audio Interface Receiver, 50 ps Jitter, 3.3V, -40 to 85 degC, 28-Pin TSSOP (PW), Green (RoHS & no Sb/Br)", Manufacturer="Texas Instruments", PartNumber=DIR9001IPWQ1, Supply Voltage(s)(V)=3.3
U9: library part CMP-0065622-1, "110 dB 2ch S/W Controlled Audio ADC With Universal Front End, DBT0030A (TSSOP-30)", Alternate Manufacturer="Texas Instruments"
U10: library part CMP-0039653-1, "16 MHz Mixed Signal Microcontroller with 16 KB Flash, 512 B SRAM and 24 GPIOs, -40 to 85 degC, 32-pin QFN (RHB), Green (RoHS & no Sb/Br)", Frequency(MHz)=16, Manufacturer="Texas Instruments", Temp Sensor=Yes
U11: library part CMP-0093065-1, "RCVR OPT DC-50MBD 1MM POF", Digikey Part Number=516-2643-ND, Manufacturer=Broadcom, Max Supply Voltage=5.25V, Min Supply Voltage=3.135V, Mouser Part Number=630-AFBR-2624Z, Operating Temperature Range="-40°C to +85°C"
U12: library part CMP-0093064-1, "Fiber Optic Transmitter with Driver 650nm 50MBd 3.135V ~ 3.465V, 4.75V ~ 5.25V 21 mA", Digikey Part Number=516-2642-ND, Manufacturer=Broadcom, Max Supply Voltage=5.25V, Min Supply Voltage=3.135V, Mouser Part Number=630-AFBR-1624Z, Operating Temperature Range="-40°C to +85°C"
Y1 Y2: library part CMP-0004590-1, "Crystal, 24.576 MHz, 10pF, SMD", Frequency Stability=+/-20ppm, Frequency_Fixed=24.576MHz, Manufacturer="Abracon Corporation", Supplier Part Number 1=535-9094-1-ND
Y3: library part CMP-0078856-1, "Crystal, 32.768 KHz, 20 ppm, SMD", Frequency Tolerance="20 ppm", Frequency_Fixed=32.768kHz, Manufacturer="ECS Inc.", Supplier Part Number 1=XC1617CT-ND

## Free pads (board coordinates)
  round 236.22 / inner round 157.48 / far side round 236.22 hole 137.8: 2(3818.9,1240) 3(137.8,137.8) 3(137.8,3366.14) 3(137.8,4980.31) 3(137.8,1771.65) 3(1200.79,452.76) 3(1203.18,1237.77) 3(1771.65,4980.31) 3(3543.31,4980.31) 3(5248.03,4980.31) 3(5984.25,1240.16) 3(6948.82,137.8) 3(6948.82,3366.14) 3(6948.82,4980.31) 3(6948.82,1770.97)
  round 82.68 hole 82.68 unplated: 5(275.59,452.76) 5(6811.02,1240.16)
  rect 60x60 hole 30: 6(620.79,1623.36) 6(1151.41,1623.36) 6(1685.2,1623.36) 6(2220.3,1623.36)
  round 80 hole 30: 6(620.79,1820.22) 6(1151.41,1820.22) 6(1685.2,1820.22) 6(2220.3,1820.22)

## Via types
v1: diameter 25, hole 12, Top Layer to Bottom Layer, 1387 vias
v2: diameter 25, hole 12, Top Layer to Bottom Layer, tented both sides, 242 vias
v3: diameter 19.68, hole 7.87, Top Layer to Bottom Layer, 29 vias

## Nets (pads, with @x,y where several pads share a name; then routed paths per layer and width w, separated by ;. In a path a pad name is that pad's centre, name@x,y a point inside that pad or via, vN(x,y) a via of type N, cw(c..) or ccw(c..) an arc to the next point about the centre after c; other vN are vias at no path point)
3.3V-ADC: C194.1 L16.1 R138.2 R142.2 | length 661.3
  Top Layer w20: v1(5368.38,4226.25) R138.2@5413.77,4226.25
  Bottom Layer w20: v1(5368.38,4226.25) 5553.7,4411.57 R142.2@5553.7,4584.29 5574.41,4605 5638.57,4605 5660.77,4582.8 C194.1@5717,4582.8
3.3V-MCU: C208.1 C209.2 C214.1 C215.1 L17.1 L18.1 L19.1 R52.2 R65.2 R66.2 R155.2 R157.2 R160.2 R161.2 U10.29 U10.30 | length 7140.9
  Top Layer w10: U10.30@5593.18,4080.24 5593.18,4102.18 v1(5603,4112) 5612.87,4102.13 U10.29@5612.87,4080.24
  Top Layer w15: v1(5216.55,3896.98) 5230.26,3910.68 R66.2@5252.91,3910.68 ; R65.2@5252.91,4014.39 5237.88,4014.39 v1(5224.86,4027.41) 5224.86,4091.18 5239.11,4105.43 R52.2@5252.91,4105.43
  Top Layer w20: v1(5933.66,4016.33) R161.2@5933.66,4056.76
  SIG04 w20: v1@5413.89,230.67 5413.89,288.27 5440.58,314.96 5655.96,314.96 5700.19,359.19 5767.41,426.41 5952.41,426.41 6140.53,614.53 6140.53,855.47 6768,1482.93 6768,3684.8 6470.8,3982 5967.98,3982 v1(5933.66,4016.33) 5933.66,4034.35 5913.36,4054.64 v1(5863.73,4054.64) 5805.53,4112.84 5603.84,4112.84 v1(5603,4112)
  Bottom Layer w15: v1@5218.6,3902.09 5224.86,3908.36 v1(5224.86,4027.41) 5225.87,4028.42 5261.74,4028.42 5295.59,3994.56 5382.83,3994.56 5428.3,4040.03 L17.1@5428.3,4072.95
  Bottom Layer w20: L19.1@5001.76,190 5056.65,190 C215.1@5059.2,187.44 5161.01,187.44 5225.45,123 5291.57,123 5307.85,139.28 L18.1@5307.85,175 5360.23,175 C214.1@5360.46,175.24 5391.37,175.24 5413.57,197.44 v1(5413.57,230.35) 5413.89,230.67 R155.2@5413.89,268.53 ; L17.1@5428.3,4072.95 C208.1@5497.8,4072.95 C209.2@5587.13,4072.95 5587.13,4096.13 v1(5603,4112) ; R157.2@5863.73,3966.33 v1(5863.73,4054.64)
3.3V-SPDIF: C175.2 C176.1 C179.2 C182.2 L15.1 Q6.2 R107.2 R111.2 R112.1 R113.1 U7.1 U8.5 U8.24 | length 6098.2
  Top Layer w16: U8.5@6107.72,4567.56 v1(6156.44,4567.56) ; v1(6285.94,4567.56) U8.24@6340,4567.56 ; R107.2@6502.24,4486.81 6523.11,4486.81 v1(6538,4471.92)
  Top Layer w20: v1(5918,4343) 5956.38,4343 R112.1@5956.38,4388.19 ; v1(6223.9,496.1) C175.2@6223.9,545 ; R111.2@6502.24,4585 v1(6543,4585) 6565,4607 Q6.2@6565,4625.2
  SIG04 w20: v1(5918,4343) 5940,4365 5940,4498.65 6008.91,4567.56 v1(6156.44,4567.56) v1(6285.94,4567.56) 6303.38,4585 v1(6543,4585) 6566.61,4561.39 6566.61,4471.92 v1(6538,4471.92) ; U7.1@6162.9,395.86 6162.9,435.1 v1(6223.9,496.1) 6223.9,832.9 6846.61,1455.61 6846.61,3775.72 6606,4016.33 6606,4418.79 6552.88,4471.92
  Bottom Layer w16: C182.2@6107.72,4567.56 v1(6156.44,4567.56) ; v1(6285.94,4567.56) C179.2@6340,4567.56
  Bottom Layer w20: L15.1@6053.36,4546.06 6069.4,4546.06 6086.96,4563.62 C182.2@6107.72,4563.62 ; v1(6156.44,4567.56) 6208.62,4567.56 6210,4568.94 6211.38,4567.56 v1(6285.94,4567.56)
14_4V: C131.2 C133.2 C135.2 C136.2 C138.1 C139.1 C146.1 C147.1 C148.1 C149.1 C150.1 C151.1 C152.1 C153.1 D1.1 D2.1 L1.2 L11.1 pad.6@620.79,1820.22 pad.6@1151.41,1820.22 pad.6@1685.2,1820.22 pad.6@2220.3,1820.22 Q1.5 Q1.6 Q1.7 Q1.8 Q1.9@823.3,1359.96 R69.2 R71.2 R81.2 R87.1 R88.1 R89.1 R90.1 U3.4 | length 6135
  Top Layer w20: v1@509,4485.24 510.24,4484 R69.2@597.85,4484 ; v1(532.52,4589.33) 537.63,4594.44 R71.2@583.79,4594.44 ; v1(1370.03,4592.78) 1371.69,4594.44 R81.2@1412.84,4594.44
  Top Layer w30: v1(2282.8,2698.05) 2290.34,2690.51 L11.1@2449.33,2690.51 ; v1(3134.69,3341.14) 3136.64,3343.09 L1.2@3180.41,3343.09
  SIG03 w20: v1(511.95,4484.91) 490.79,4506.07 449.26,4506.07 ; v1(534.42,1900.5) 366,2068.92 366,4422.81 449.26,4506.07 ; v1(1370.03,4592.78) 1311.64,4651.17 594.36,4651.17 v1(532.52,4589.33) 449.26,4506.07
  SIG03 w30: v1(2220.69,1900.5) 2220.69,2640.03 v1(2241.63,2660.98) ; v1(2282.8,2698.05) 2925.89,3341.14 v1(3134.69,3341.14)
  Bottom Layer w15: v1(884.1,1582.6) 911.48,1555.21 U3.4@931.57,1555.21
  other v1: 566.85,1333.87 626.85,1333.87 686.85,1333.87 566.85,1380 626.85,1380 686.85,1380 566.85,1426.13 626.85,1426.13 686.85,1426.13 534.42,1739.64 704.9,1739.64 1065.03,1739.64 1235.51,1739.64 1598.82,1739.64 1769.3,1739.64 2133.92,1739.64 2304.4,1739.64 534.42,1820.22 704.9,1820.22 1065.03,1820.22 1235.51,1820.22 1598.82,1820.22 1769.3,1820.22 2133.92,1820.22 2304.4,1820.22 621.18,1900.5 704.9,1900.5 1065.03,1900.5 1151.8,1900.5 1235.51,1900.5 1598.82,1900.5 1685.58,1900.5 1769.3,1900.5 2133.92,1900.5 2304.4,1900.5 1478.61,2209.67 1543.92,2209.67 1603.76,2209.67 1663.59,2209.67 1723.43,2209.67 790.18,2210.44 850.49,2210.44 910.33,2210.44 970.16,2210.44 1030,2210.44 1020.11,2265.67 1543.92,2265.47 1603.76,2265.47 1663.59,2265.47 1713.43,2265.47 850.49,2266.24 910.33,2266.24 970.16,2266.24 850.49,2322.03 1543.92,2321.26 1543.92,2377.05 850.49,2377.83 1543.92,2432.85 850.49,2433.62 851.19,2476.16 1543.92,2476.16 2283.28,2660.98 2241.39,2697.81
\FAULT1: R6.1 R158.1 U1.61 | length 1831.5
  Top Layer w10: U1.61@4065.2,3291.73 4124.3,3291.73 v1(4127.82,3295.26) 4135.65,3303.09 R6.1@4171.31,3303.09 ; v1(5487,3736.46) R158.1@5487,3771.38
  SIG04 w10: v1(4127.82,3295.26) 4155.36,3295.26 4163.2,3303.09 4163.2,3358.95 4206.85,3402.6 4788.91,3402.6 4849.88,3463.57 v1(4931.25,3463.57) ; v1(4975,3697) 5014.46,3736.46 v1(5487,3736.46)
  Bottom Layer w10: v1(4931.25,3463.57) 4931.25,3653.25 v1(4975,3697)
\FAULT2: R35.1 R159.1 U2.61 | length 1253.8
  Top Layer w10: v1(5535.38,3736.46) R159.1@5535.38,3771.38 ; U2.61@6132.55,3291.73 6191.65,3291.73 v1(6195.18,3295.26) 6203.01,3303.09 R35.1@6238.67,3303.09
  SIG04 w10: v1(5535.38,3736.46) 5581.35,3690.5 5671.12,3690.5 5690.62,3671 6196.04,3671 v1(6212.04,3655)
  SIG03 w10: v1(6195.18,3295.26) 6213.2,3295.26 6236.63,3318.68 6236.63,3630.41 v1(6212.04,3655)
\STBY1: R4.1 R147.2 U1.60 | length 1889.8
  Top Layer w10: U1.60@4065.2,3260.24 4127.25,3260.24 v1(4128.92,3258.57) 4170.79,3258.57 R4.1@4171.31,3259.09 ; v1(5401.06,3921.68) R147.2@5401.06,3956.22
  SIG04 w10: v1(4128.92,3258.57) 4165.52,3258.57 4199.85,3292.9 4199.85,3356.7 4227.33,3384.18 4821.18,3384.18 v1(4869,3432) ; v1(4870,3713) 5013.3,3856.3 5335.67,3856.3 v1(5401.06,3921.68)
  Bottom Layer w10: v1(4869,3432) 4869,3712 v1(4870,3713)
\STBY2: R33.1 R146.2 U2.60 | length 1534.3
  Top Layer w10: v1(5401.06,3852) R146.2@5401.06,3886.54 ; U2.60@6132.55,3260.24 6194.6,3260.24 v1(6196.27,3258.57) 6238.15,3258.57 R33.1@6238.67,3259.09
  SIG04 w10: v1(5401.06,3852) 5443.63,3809.43 5662.96,3809.43 5724.51,3747.88 6190.33,3747.88 v1(6213.34,3724.87)
  SIG03 w10: v1(6196.27,3258.57) 6216.99,3258.57 6264.42,3306 6264.42,3673.8 v1(6213.34,3724.87)
Audio_IN1+: C190.1 J1.10 R128.2 | length 747.9
  Top Layer w20: v1(2387.8,674.43) R128.2@2387.8,708.11
  SIG04 w20: v1(2387.8,674.43) 2371.16,657.8 2304.17,590.8 2304.17,277.42 v1(2374.56,207.03) v1(2437.56,207.03)
  Bottom Layer w16: J1.10@2406,123 C190.1@2406,243
Audio_IN1-: C192.1 J1.9 R130.2 | length 508.9
  Top Layer w20: v1(2427.8,674.43) R130.2@2427.8,708.11
  SIG04 w20: v1(2427.8,674.43) 2427.8,665.8 2387,625 2332.65,570.65 2332.65,480.77 v1(2374.44,438.97) v1(2437.44,438.97)
  Bottom Layer w16: C192.1@2406,403 J1.9@2406,523
Audio_IN2+: C191.1 J1.12 R129.2 | length 715.5
  Top Layer w20: v1(2498.8,674.43) R129.2@2498.8,708.11
  SIG04 w20: v1(2498.8,674.43) 2498.8,282.79 v1(2574.56,207.03) v1(2637.56,207.03)
  Bottom Layer w16: J1.12@2606,123 C191.1@2606,243
Audio_IN2-: C193.1 J1.11 R131.2 | length 466.7
  Top Layer w20: v1(2539.21,674.43) R131.2@2539.21,708.11
  SIG04 w20: v1(2539.21,674.43) 2539.21,474.2 v1(2574.44,438.97) v1(2637.44,438.97)
  Bottom Layer w16: C193.1@2606,403 J1.11@2606,523
BAT_IN: C117.1 C119.1 C121.1 C122.1 J1.1 J1.3 J1.5 J1.7 L10.1 | length 251.7
  Bottom Layer w10: C121.1@1605.9,397.66 C121.1@1606,397.56
  Bottom Layer w19.68: C121.1@1606,397.56 J1.1@1606,523 ; C122.1@1804.28,397.56 1804.28,521.28 J1.3@1806,523
  other v1: 795,673.87 845,673.87 895,673.87 945,673.87 795,720 845,720 895,720 945,720 795,766.13 845,766.13 895,766.13 945,766.13
ClassH_tracking: R5.1 R64.1 U1.10 U2.10 | length 3889.5
  Top Layer w10: U1.10@3717.76,3450.2 v1(3717.76,3518.75) 3717.76,3518.96 R5.1@3770.9,3572.11 ; U2.10@5785.11,3450.2 v1(5785.11,3518.96)
  SIG04 w10: v1(3134.06,3614.74) 3153.32,3634 3655.86,3634 3717.76,3572.11 ; v1(3717.76,3518.75) 3717.76,3572.11 ; v1(5785.11,3518.96) 5634.82,3669.25 3814.89,3669.25 3717.76,3572.11
  SIG03 w10: v1@2455.41,3915.9 v1(2460.69,3915.9) 2465.96,3915.9 2767.12,3614.74 v1(3134.06,3614.74)
  Bottom Layer w10: R64.1@2427.76,3915.9 v1(2460.69,3915.9)
COMP: C118.1 C120.1 U4.11 U5.11 | length 1284.4
  Top Layer w10: U4.11@994.17,4378.22 994.17,4351.48 v1(1004.43,4341.22) ; U5.11@1837.8,4377.83 1872.38,4377.83 1887.15,4363.07 v1(1896.23,4353.99)
  SIG03 w10: v1(1004.43,4341.22) 1027.14,4318.52 1860.76,4318.52 v1(1896.23,4353.99)
  Bottom Layer w10: C120.1@799.04,4293.5 870.27,4293.5 C118.1@911.11,4252.66 999.67,4341.22 v1(1004.43,4341.22)
CSN1: C130.2 R91.2 U4.3 | length 2934.4
  Top Layer w10: v1@679.8,4584.63 C130.2@704.85,4584.63 732.12,4557.36 U4.3@761.89,4557.36
  SIG04 w6: v1(677,4585) 380.65,4288.65 380.65,3018.64 411.31,2987.98 617.63,2781.66 734.45,2781.66 1141.65,2374.46 v1(1141.65,2295.99)
  Bottom Layer w6: R91.2@1123.69,2334.12 1123.69,2313.95 v1(1141.65,2295.99)
CSN2: C142.2 R92.2 U5.3 | length 3301.9
  Top Layer w10: v1(1511.32,4585) 1511.7,4584.63 C142.2@1541.97,4584.63 1546.95,4584.63 1574.61,4556.96 U5.3@1605.51,4556.96
  SIG04 w6: v1(1511.32,4585) 1566.49,4640.17 2091.27,4640.17 2146.14,4585.3 2146.14,2524.47 1916.82,2295.15 v1(1835.77,2295.15)
  Bottom Layer w6: R92.2@1818.07,2337.36 1818.07,2312.86 v1(1835.77,2295.15)
CSP1: C130.1 R87.2 U4.4 | length 2957.8
  Top Layer w10: v1@680.09,4545.26 C130.1@704.85,4545.26 ; C130.1@712.79,4547.49 728.51,4531.77 U4.4@761.89,4531.77
  SIG04 w6: v1(677,4545) 652.56,4545 391.65,4284.09 391.65,3023.2 622.18,2792.66 739,2792.66 1154.55,2377.11 1154.55,2324.87 1177.63,2301.79 1177.63,2279.79 v1(1162.48,2264.63)
  Bottom Layer w6: R87.2@1099.33,2267.44 1159.67,2267.44 v1(1162.48,2264.63)
CSP2: C142.1 R88.2 U5.4 | length 3434.6
  Top Layer w10: v1(1511.7,4545.26) C142.1@1541.97,4545.26 1558.96,4545.26 1572.85,4531.37 U5.4@1605.51,4531.37
  SIG04 w6: v1(1511.7,4545.26) 1504.23,4545.26 1483.29,4566.19 1483.29,4602.17 1532.29,4651.17 2095.82,4651.17 2157.14,4589.85 2157.14,2519.92 1897.98,2260.75 v1(1869.61,2260.75)
  Bottom Layer w6: R88.2@1793.61,2264.6 1865.76,2264.6 v1(1869.61,2260.75)
DVDD_RET1: C13.1 R12.2 R14.1 U1.2 | length 192.4
  Top Layer w15: U1.2@3970.01,3450.48 U1.2@3969.72,3450.2 3969.72,3497.92 3991,3519.2 C13.1@3991,3529.32 3996.91,3535.23 R14.1@3996.91,3575.37
  Bottom Layer w15: v1(3971.75,3494.26) 3987.59,3478.42 R12.2@3987.59,3445.28
DVDD_RET2: C71.1 R41.2 R43.1 U2.2 | length 190.7
  Top Layer w15: U2.2@6037.36,3450.48 U2.2@6037.08,3450.2 6037.08,3497.92 6058.36,3519.2 C71.1@6058.36,3529.32 ; C71.1@6061.7,3530.82 6063.61,3532.72 R43.1@6063.61,3576.86
  Bottom Layer w15: v1(6039.1,3494.26) 6054.95,3478.42 R41.2@6054.95,3445.28
FB: C120.2 R61.2 R62.1 R63.2 R75.1 U4.10 | length 438
  Top Layer w10: v1(713.06,4370.86) 720.42,4378.22 U4.10@761.89,4378.22
  Bottom Layer w10: R62.1@739.99,4245.77 R61.2@739.99,4343 R63.2@676.68,4343 677,4343.32 677,4363.07 684.79,4370.86 v1(713.06,4370.86) 716.52,4374.32 834.59,4374.32 R75.1@865.09,4343.82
